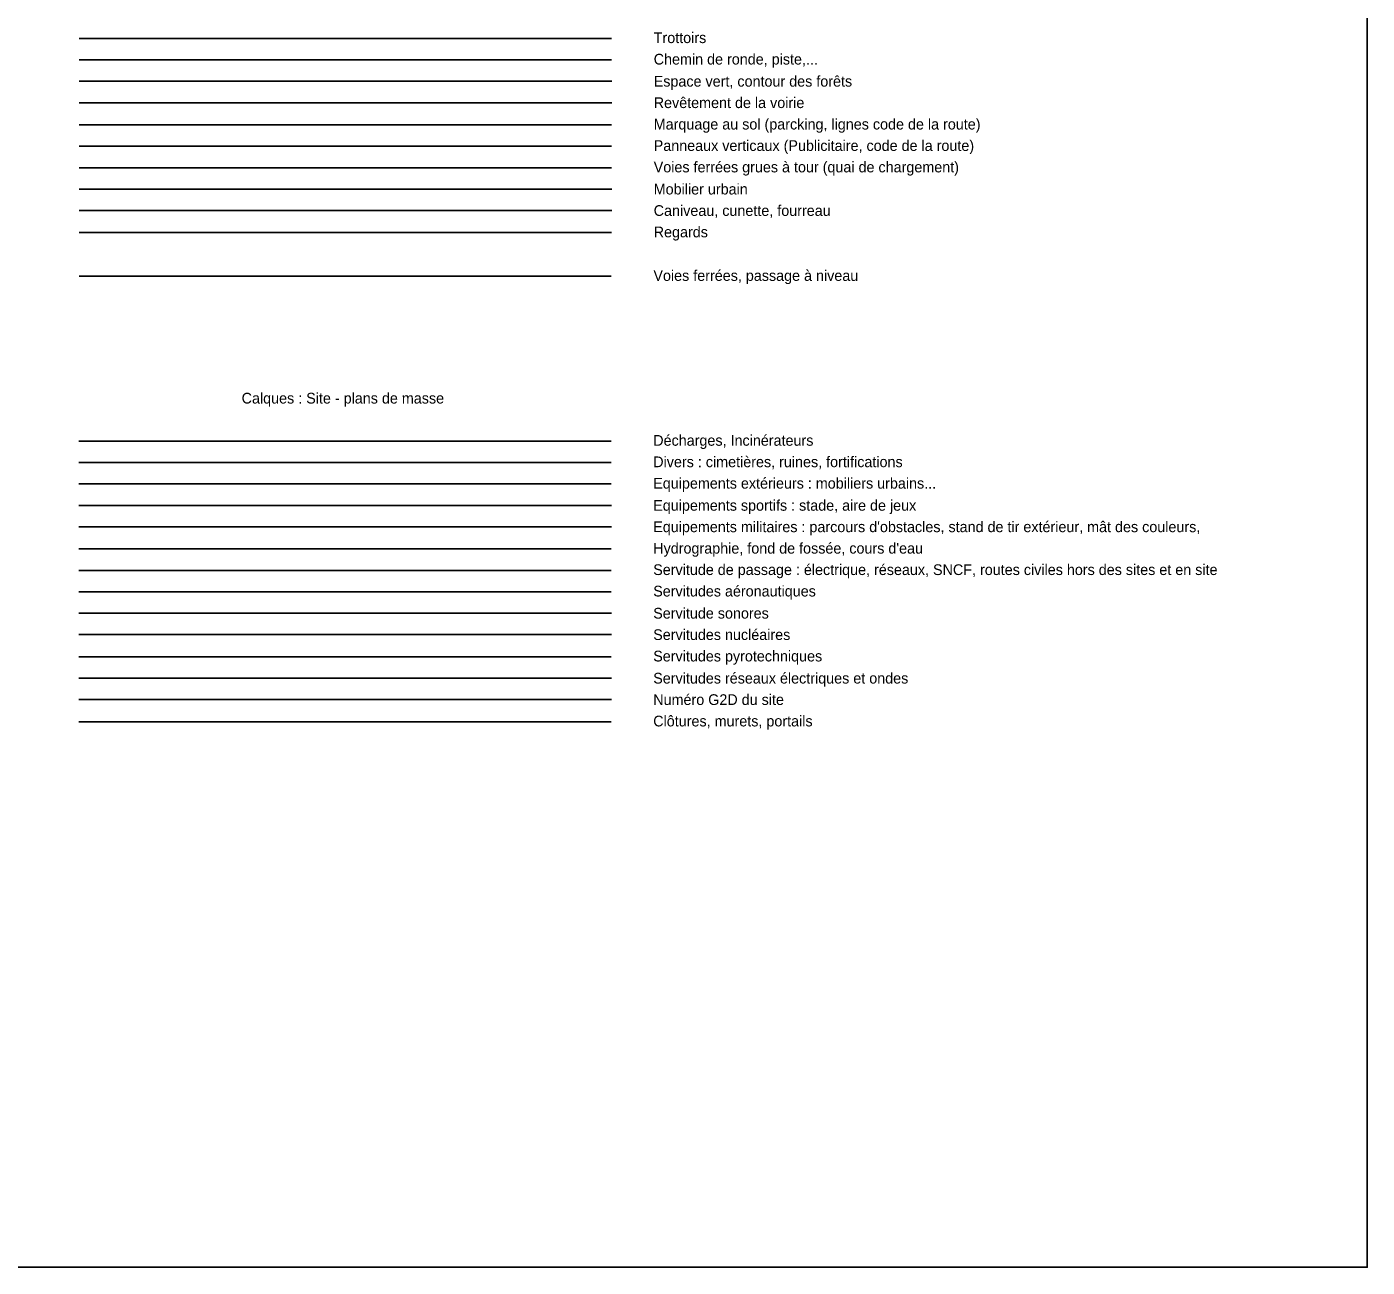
# Model space of a CAD drawing. Extents: x 703432 to 707394, y 7057985 to 7059523.
# Drawn here: x 707262 to 707324.5, y 7058419.6 to 7058477.4 of the extents above; entities that cross this region are included whole.
import ezdxf

# ---------------------------------------------------------------- set-up
doc = ezdxf.new("R2010")
doc.units = 0
for name, color, linetype in [('DH_CADRE -CARTOUCHE', 7, 'Continuous'), ('SITE _DIVERS', 7, 'Continuous'), ('SITE _EQUIP EXTERIEUR', 7, 'Continuous'), ('SITE _EQUIP MILITAIRE', 7, 'Continuous'), ('SITE _EQUIP_SPORTIF', 7, 'Continuous'), ('SITE _HYDROGRAPHIE', 7, 'Continuous'), ('SITE _LIMITE_PHYSIQUE', 7, 'Continuous'), ('SITE _SERVITUDE', 7, 'Continuous'), ('SITE _SERVITUDE AERO', 7, 'Continuous'), ('SITE _SERVITUDE BRUIT', 7, 'Continuous'), ('SITE _SERVITUDE NUCL', 7, 'Continuous'), ('SITE _SERVITUDE PYRO', 7, 'Continuous'), ('SITE _SERVITUDE RADIO ELEC', 7, 'Continuous'), ('SITE_CODE_G2D', 7, 'Continuous'), ('SITE_DECHARGE', 7, 'Continuous'), ('VOIRIE TROTTOIR', 7, 'Continuous'), ('VOIRIE_CANIVEAU_TECHNIQUE', 7, 'Continuous'), ('VOIRIE_CHEMIN', 7, 'Continuous'), ('VOIRIE_ESPACE VERT', 7, 'Continuous'), ('VOIRIE_MOBILIER_URBAIN', 7, 'Continuous'), ('VOIRIE_REGARD', 7, 'Continuous'), ('VOIRIE_ROUTE_REVETEMENT', 7, 'Continuous'), ('VOIRIE_SIGNAL HORIZON', 7, 'Continuous'), ('VOIRIE_SIGNAL VERTIC', 7, 'Continuous'), ('VOIRIE_VOIES FERREES', 7, 'Continuous'), ('VOIRIE_VOIES GRUE', 7, 'Continuous')]:
    doc.layers.add(name, color=color, linetype=linetype)

msp = doc.modelspace()

# ---------------------------------------------------------------- linework, layer by layer
at = {"layer": 'DH_CADRE -CARTOUCHE'}
msp.add_lwpolyline([(707199.469, 7058644.551), (707324.469, 7058644.551), (707324.469, 7058419.551), (707199.469, 7058419.551)], close=True, dxfattribs=at)
at = {"layer": 'SITE _DIVERS'}
msp.add_line((707264.395, 7058457.089), (707289.21, 7058457.089), dxfattribs=at)
at = {"layer": 'SITE _EQUIP EXTERIEUR'}
msp.add_line((707264.395, 7058456.089), (707289.21, 7058456.089), dxfattribs=at)
at = {"layer": 'SITE _EQUIP MILITAIRE'}
msp.add_line((707264.395, 7058454.089), (707289.225, 7058454.089), dxfattribs=at)
at = {"layer": 'SITE _EQUIP_SPORTIF'}
msp.add_line((707264.395, 7058455.089), (707289.225, 7058455.089), dxfattribs=at)
at = {"layer": 'SITE _HYDROGRAPHIE'}
msp.add_line((707264.395, 7058453.058), (707289.21, 7058453.058), dxfattribs=at)
at = {"layer": 'SITE _LIMITE_PHYSIQUE'}
msp.add_line((707264.395, 7058444.996), (707289.21, 7058444.996), dxfattribs=at)
at = {"layer": 'SITE _SERVITUDE'}
msp.add_line((707264.395, 7058452.058), (707289.21, 7058452.058), dxfattribs=at)
at = {"layer": 'SITE _SERVITUDE AERO'}
msp.add_line((707264.395, 7058451.058), (707289.21, 7058451.058), dxfattribs=at)
at = {"layer": 'SITE _SERVITUDE BRUIT'}
msp.add_line((707264.395, 7058450.058), (707289.225, 7058450.058), dxfattribs=at)
at = {"layer": 'SITE _SERVITUDE NUCL'}
msp.add_line((707264.395, 7058449.058), (707289.225, 7058449.058), dxfattribs=at)
at = {"layer": 'SITE _SERVITUDE PYRO'}
msp.add_line((707264.395, 7058448.027), (707289.21, 7058448.027), dxfattribs=at)
at = {"layer": 'SITE _SERVITUDE RADIO ELEC'}
msp.add_line((707264.395, 7058447.027), (707289.225, 7058447.027), dxfattribs=at)
at = {"layer": 'SITE_CODE_G2D'}
msp.add_line((707264.395, 7058446.027), (707289.225, 7058446.027), dxfattribs=at)
at = {"layer": 'SITE_DECHARGE'}
msp.add_line((707264.395, 7058458.089), (707289.21, 7058458.089), dxfattribs=at)
at = {"layer": 'VOIRIE TROTTOIR'}
msp.add_line((707264.417, 7058476.872), (707289.232, 7058476.872), dxfattribs=at)
at = {"layer": 'VOIRIE_CANIVEAU_TECHNIQUE'}
msp.add_line((707264.417, 7058468.841), (707289.247, 7058468.841), dxfattribs=at)
at = {"layer": 'VOIRIE_CHEMIN'}
msp.add_line((707264.417, 7058475.872), (707289.232, 7058475.872), dxfattribs=at)
at = {"layer": 'VOIRIE_ESPACE VERT'}
msp.add_line((707264.417, 7058474.872), (707289.247, 7058474.872), dxfattribs=at)
at = {"layer": 'VOIRIE_MOBILIER_URBAIN'}
msp.add_line((707264.417, 7058469.841), (707289.247, 7058469.841), dxfattribs=at)
at = {"layer": 'VOIRIE_REGARD'}
msp.add_line((707264.417, 7058467.81), (707289.232, 7058467.81), dxfattribs=at)
at = {"layer": 'VOIRIE_ROUTE_REVETEMENT'}
msp.add_line((707264.417, 7058473.872), (707289.247, 7058473.872), dxfattribs=at)
at = {"layer": 'VOIRIE_SIGNAL HORIZON'}
msp.add_line((707264.417, 7058472.841), (707289.232, 7058472.841), dxfattribs=at)
at = {"layer": 'VOIRIE_SIGNAL VERTIC'}
msp.add_line((707264.417, 7058471.841), (707289.232, 7058471.841), dxfattribs=at)
at = {"layer": 'VOIRIE_VOIES FERREES'}
msp.add_line((707264.417, 7058465.779), (707289.217, 7058465.779), dxfattribs=at)
at = {"layer": 'VOIRIE_VOIES GRUE'}
msp.add_line((707264.417, 7058470.841), (707289.232, 7058470.841), dxfattribs=at)

# ---------------------------------------------------------------- texts
at = {"layer": 'DH_CADRE -CARTOUCHE'}
msp.add_text(' Calques : Site - plans de masse', height=0.5, dxfattribs=at).set_placement((707271.8, 7058459.839))
at = {"layer": 'SITE _DIVERS'}
msp.add_text('Divers : cimetières, ruines, fortifications', height=0.5, dxfattribs=at).set_placement((707291.178, 7058456.87))
at = {"layer": 'SITE _EQUIP EXTERIEUR'}
msp.add_text('Equipements extérieurs : mobiliers urbains...', height=0.5, dxfattribs=at).set_placement((707291.178, 7058455.87))
at = {"layer": 'SITE _EQUIP MILITAIRE'}
msp.add_text("Equipements militaires : parcours d'obstacles, stand de tir extérieur, mât des couleurs,", height=0.5, dxfattribs=at).set_placement((707291.178, 7058453.839))
at = {"layer": 'SITE _EQUIP_SPORTIF'}
msp.add_text('Equipements sportifs : stade, aire de jeux', height=0.5, dxfattribs=at).set_placement((707291.178, 7058454.839))
at = {"layer": 'SITE _HYDROGRAPHIE'}
msp.add_text("Hydrographie, fond de fossée, cours d'eau", height=0.5, dxfattribs=at).set_placement((707291.178, 7058452.839))
at = {"layer": 'SITE _LIMITE_PHYSIQUE'}
msp.add_text('Clôtures, murets, portails', height=0.5, dxfattribs=at).set_placement((707291.178, 7058444.777))
at = {"layer": 'SITE _SERVITUDE'}
msp.add_text('Servitude de passage : électrique, réseaux, SNCF, routes civiles hors des sites et en site', height=0.5, dxfattribs=at).set_placement((707291.178, 7058451.839))
at = {"layer": 'SITE _SERVITUDE AERO'}
msp.add_text('Servitudes aéronautiques', height=0.5, dxfattribs=at).set_placement((707291.178, 7058450.839))
at = {"layer": 'SITE _SERVITUDE BRUIT'}
msp.add_text('Servitude sonores', height=0.5, dxfattribs=at).set_placement((707291.178, 7058449.808))
at = {"layer": 'SITE _SERVITUDE NUCL'}
msp.add_text('Servitudes nucléaires', height=0.5, dxfattribs=at).set_placement((707291.178, 7058448.808))
at = {"layer": 'SITE _SERVITUDE PYRO'}
msp.add_text('Servitudes pyrotechniques', height=0.5, dxfattribs=at).set_placement((707291.178, 7058447.808))
at = {"layer": 'SITE _SERVITUDE RADIO ELEC'}
msp.add_text('Servitudes réseaux électriques et ondes', height=0.5, dxfattribs=at).set_placement((707291.178, 7058446.777))
at = {"layer": 'SITE_CODE_G2D'}
msp.add_text('Numéro G2D du site', height=0.5, dxfattribs=at).set_placement((707291.178, 7058445.777))
at = {"layer": 'SITE_DECHARGE'}
msp.add_text('Décharges, Incinérateurs', height=0.5, dxfattribs=at).set_placement((707291.178, 7058457.87))
at = {"layer": 'VOIRIE TROTTOIR'}
msp.add_text('Trottoirs', height=0.5, dxfattribs=at).set_placement((707291.2, 7058476.653))
at = {"layer": 'VOIRIE_CANIVEAU_TECHNIQUE'}
msp.add_text('Caniveau, cunette, fourreau', height=0.5, dxfattribs=at).set_placement((707291.2, 7058468.591))
at = {"layer": 'VOIRIE_CHEMIN'}
msp.add_text('Chemin de ronde, piste,...', height=0.5, dxfattribs=at).set_placement((707291.2, 7058475.653))
at = {"layer": 'VOIRIE_ESPACE VERT'}
msp.add_text('Espace vert, contour des forêts', height=0.5, dxfattribs=at).set_placement((707291.2, 7058474.622))
at = {"layer": 'VOIRIE_MOBILIER_URBAIN'}
msp.add_text('Mobilier urbain', height=0.5, dxfattribs=at).set_placement((707291.2, 7058469.591))
at = {"layer": 'VOIRIE_REGARD'}
msp.add_text('Regards', height=0.5, dxfattribs=at).set_placement((707291.2, 7058467.591))
at = {"layer": 'VOIRIE_ROUTE_REVETEMENT'}
msp.add_text('Revêtement de la voirie', height=0.5, dxfattribs=at).set_placement((707291.2, 7058473.622))
at = {"layer": 'VOIRIE_SIGNAL HORIZON'}
msp.add_text('Marquage au sol (parcking, lignes code de la route)', height=0.5, dxfattribs=at).set_placement((707291.2, 7058472.622))
at = {"layer": 'VOIRIE_SIGNAL VERTIC'}
msp.add_text('Panneaux verticaux (Publicitaire, code de la route)', height=0.5, dxfattribs=at).set_placement((707291.2, 7058471.622))
at = {"layer": 'VOIRIE_VOIES FERREES'}
msp.add_text('Voies ferrées, passage à niveau', height=0.5, dxfattribs=at).set_placement((707291.186, 7058465.56))
at = {"layer": 'VOIRIE_VOIES GRUE'}
msp.add_text('Voies ferrées grues à tour (quai de chargement)', height=0.5, dxfattribs=at).set_placement((707291.2, 7058470.622))

doc.saveas('drawing.dxf')
